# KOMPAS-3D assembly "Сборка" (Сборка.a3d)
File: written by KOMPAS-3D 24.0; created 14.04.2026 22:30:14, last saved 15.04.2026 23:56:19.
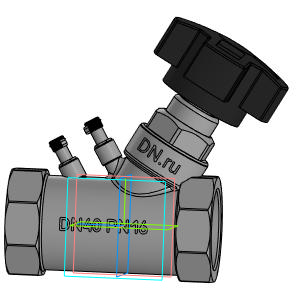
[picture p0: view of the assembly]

Document properties: Автор: tyuri; Полное имя файла: D:\Аутсорс\VB0000P-T Клапан балансировочный статический DN.ru\DN40\Исходные данные\Сборка.a3d

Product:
- Component [detail]: Деталь1  | qty 1  | Автор: tyuri; additional columns: Типовые; source file: Деталь1 - Деталь1.m3d
- Body: Тело 1  | qty 1
    Масса: 1.435437
- Component [detail]: Ручка  | designation Деталь2  | qty 1  | Масса: 0.541971; Автор: tyuri; additional columns: Типовые; source file: Деталь2 - Деталь2.m3d
- Part/product: Сборка
    Масса: 1.977408

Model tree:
1. Эскиз:2  (labels: Грань.Твердое тело1)
2. Элемент вращения:1  (labels: Грань.Твердое тело1)
     Угол 1 = 360
3. Смещенная плоскость:1
     Расстояние = 40
4. Эскиз:3
5. Элемент выдавливания:1  (with: Грань.Элемент вращения:1)
     Расстояние 1 = -19.9877; Смещение 1 = 0.01
6. Эскиз:4
7. Элемент выдавливания:2  (with: Грань.Элемент вращения:1)  (labels: Грань.Твердое тело1; Ребро.Твердое тело1; Твердое тело1)
     Расстояние 1 = -16.0112; Смещение 1 = 0.001; Ориентация = 2; Расстояние = 2

Referenced files in D:\Аутсорс\VB0000P-T Клапан балансировочный статический DN.ru\DN40\Исходные данные\: Деталь1 - Деталь1.m3d, Деталь2 - Деталь2.m3d
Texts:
  DN40 PN16
  GOST 26.020 Pr3
  Деталь1 Деталь1
  Деталь2 Ручка
  Ось X.Начало координат
  Ось Z.Начало координат
  Плоскость ZY.Начало координат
